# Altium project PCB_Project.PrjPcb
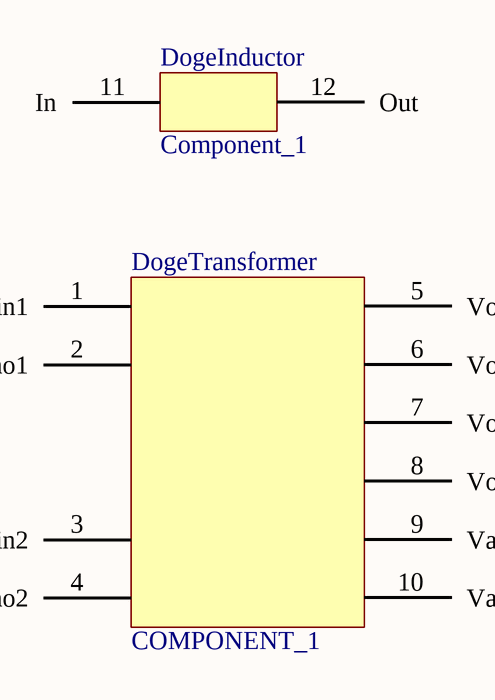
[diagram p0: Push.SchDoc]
1 sheet, 2 parts. Net scope: global (net labels, ports and power ports of the same name join across sheets).
Board file: PCB_push.PcbDoc

## Sheet Push.SchDoc
size A4; SheetNumber: 1; SheetTotal: 1

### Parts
DogeInductor  Component_1  [inductor]
DogeTransformer  COMPONENT_1  [transformer]

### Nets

Not connected (* = marked no-connect by the designer): DogeInductor 11(In) 12(Out); DogeTransformer 1(Vin1) 2(Vino1) 3(Vin2) 4(Vino2) 5(Vout1) 6(Vouto1) 7(Vout2) 8(Vouto2) 9(Vaux) 10(Vauxo)

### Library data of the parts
DogeInductor = Component_1: Doge
DogeTransformer = COMPONENT_1: Doge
